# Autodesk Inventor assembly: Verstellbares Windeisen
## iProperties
Created: 2008-02
Part Number: Verstellbares Windeisen
Document SubType Name: Assembly
Designer: Benno
Manufacturer: Standard
Standards Organization: Custom
Author: Benno
